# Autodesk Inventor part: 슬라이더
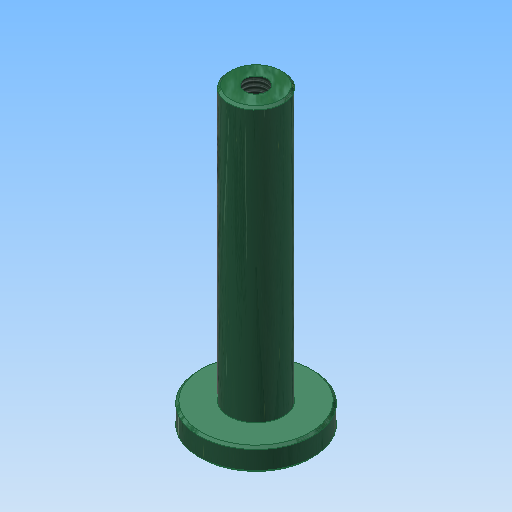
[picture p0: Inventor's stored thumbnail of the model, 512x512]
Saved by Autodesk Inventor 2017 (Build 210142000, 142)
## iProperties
Created: 2016-02
Part Number: 슬라이더
Material: 스테인리스강
Document SubType Name: Modeling
Designer: mduedu
Density: 8.08 g/cm^3
Appearance: 매끄러움 - 짙은 바다 녹색
Author: mduedu
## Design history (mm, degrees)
sketch "스케치1"
  geometry: C1 r 12.5 at (0, 0); 1 further point
  constraints: 1 centre point, 1 coincident
  dimensions: "d0" = 25 diameter of C1
extrude "돌출1" new body sketch "스케치1" distance "d1" = 5; taper "d2" = 0 deg
sketch "스케치2"
  geometry: C1 r 6 at (0, 0); 1 further point
  constraints: 1 centre point, 1 coincident
  dimensions: "d3" = 12 diameter of C1
extrude "돌출2" join sketch "스케치2" distance "d4" = 60; taper "d5" = 0 deg
chamfer "모따기1" distance "d6" = 0.5; stored, may be unused: second distance "d7" = 2, angle "d8" = 45 deg
hole "구멍1" diameter "d11" = 4.917; stored, may be unused: countersink angle "d15" = 90 deg, drill point angle "d17" = 118 deg; dims "d9" = 10, "d10" = 10, "d12" = 10, "d13" = 4, "d14" = 2, "d16" = 12
chamfer "모따기2" distance "d18" = 0.5; stored, may be unused: second distance "d19" = 2, angle "d20" = 45 deg
sketch "스케치3"
  geometry: L1 (-12.5, 4.5)-(-12, 5) reference; L2 (-12, 5)-(-6, 5) reference; L3 (-6, 5)-(-6, 64.5) reference; L4 (-6, 64.5)-(-5.5, 65) reference; L5 (-5.5, 65)-(-2.458, 65) reference; L6 (-2.458, 65)-(-2.458, 53) reference; L7 (-2.458, 53)-(0, 51.523) reference; L8 (0, 51.523)-(2.458, 53) reference; L9 (2.458, 53)-(2.458, 65) reference; L10 (2.458, 65)-(5.5, 65) reference; L11 (5.5, 65)-(6, 64.5) reference; L12 (6, 64.5)-(6, 5) reference; L13 (6, 5)-(12, 5) reference; L14 (12, 5)-(12.5, 4.5) reference; L15 (12.5, 4.5)-(12.5, 0.5) reference; L16 (12.5, 0.5)-(12, 0) reference; L17 (12, 0)-(-12, 0) reference; L18 (-12, 0)-(-12.5, 0.5) reference; L19 (-12.5, 0.5)-(-12.5, 4.5) reference; 1 further point
  node "절단 모서리 투영1"
node "솔리드1"
